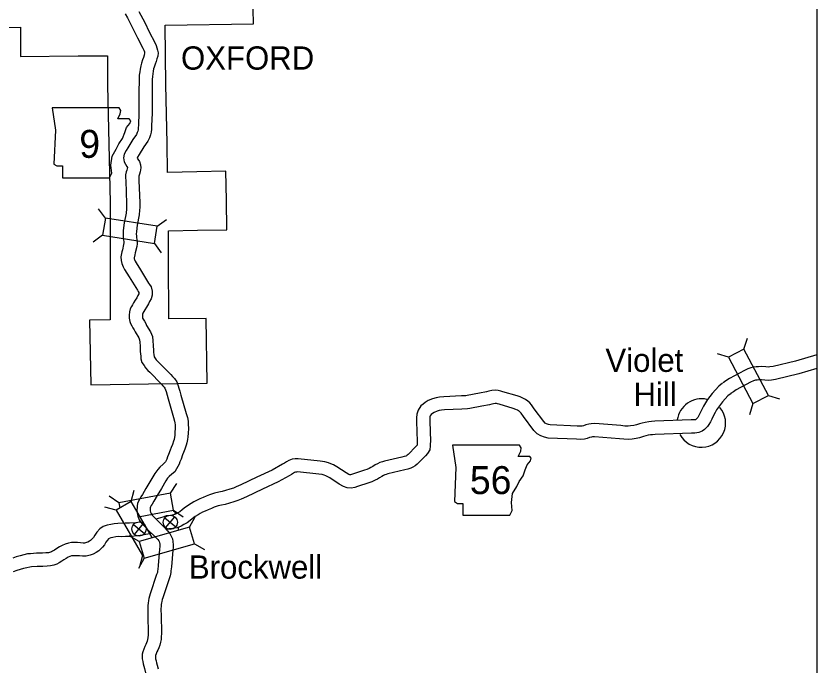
# Model space of a CAD drawing. Extents: x 1377389 to 1380723, y 1168351 to 1170484.
# Drawn here: x 1378097.6 to 1378279.2, y 1169964.7 to 1170112.1 of the extents above; entities that cross this region are included whole.
import ezdxf

# ---------------------------------------------------------------- set-up
doc = ezdxf.new("R2010")
doc.units = 0
doc.layers.add('B_Fill', color=7, linetype='Continuous')
doc.layers.add('B_Text', color=7, linetype='Continuous')

msp = doc.modelspace()

# ---------------------------------------------------------------- linework, layer by layer
at = {"layer": 'B_Fill'}
for p, q in [((1378117.86, 1170066.24), (1378116.31, 1170068.37)), ((1378129.59, 1170064.38), (1378131.73, 1170065.93)), ((1378117.24, 1170062.33), (1378115.1, 1170060.78)), ((1378128.97, 1170060.47), (1378130.52, 1170058.33)), ((1378262.6, 1170036.5), (1378263.38, 1170039.02)), ((1378259.09, 1170034.66), (1378256.57, 1170035.44)), ((1378268.13, 1170025.99), (1378270.65, 1170025.21)), ((1378264.62, 1170024.15), (1378263.84, 1170021.62)), ((1378132.59, 1170003.85), (1378134.08, 1170006.03)), ((1378120.91, 1170001.67), (1378118.74, 1170003.16)), ((1378132.59, 1170003.85), (1378120.91, 1170001.67)), ((1378123.74, 1170001.98), (1378124.42, 1170004.53)), ((1378133.32, 1169999.96), (1378132.59, 1170003.85)), ((1378123.74, 1170001.98), (1378120.31, 1169999.99)), ((1378120.91, 1170001.67), (1378121.13, 1170000.53)), ((1378128.46, 1169993.82), (1378123.74, 1170001.98)), ((1378120.31, 1169999.99), (1378117.76, 1170000.68)), ((1378120.31, 1169999.99), (1378126.26, 1169989.71)), ((1378125.75, 1169998.54), (1378133.32, 1169999.96)), ((1378133.32, 1169999.96), (1378135.5, 1169998.46)), ((1378131.32, 1169998.28), (1378133.81, 1169996.19)), ((1378131.52, 1169995.99), (1378133.61, 1169998.48)), ((1378136.96, 1169996.14), (1378138.24, 1169998.45)), ((1378124.24, 1169996.77), (1378126.73, 1169994.68)), ((1378124.44, 1169994.48), (1378126.53, 1169996.97)), ((1378136.96, 1169996.14), (1378125.53, 1169992.88)), ((1378138.04, 1169992.33), (1378136.96, 1169996.14)), ((1378125.53, 1169992.88), (1378123.23, 1169994.16)), ((1378125.53, 1169992.88), (1378126.62, 1169989.07)), ((1378126.62, 1169989.07), (1378138.04, 1169992.33)), ((1378138.04, 1169992.33), (1378140.35, 1169991.05)), ((1378126.62, 1169989.07), (1378125.34, 1169986.76)), ((1378126.26, 1169989.71), (1378125.58, 1169987.16)), ((1378126.26, 1169989.71), (1378126.37, 1169989.78))]:
    msp.add_line(p, q, dxfattribs=at)
for points in [[(1378145.34, 1170070.27), (1378145.19, 1170076.89), (1378138.59, 1170076.75), (1378131.98, 1170076.61), (1378131.84, 1170083.24), (1378131.57, 1170096.49), (1378131.44, 1170109.98), (1378151.44, 1170110.32), (1378151.3, 1170117.04)], [(1378122.31, 1170112.59), (1378122.84, 1170111.64), (1378124.1, 1170109.24), (1378125.12, 1170107.14), (1378126.36, 1170104.8), (1378126.56, 1170104.3), (1378126.7, 1170103.94), (1378126.75, 1170103.75), (1378126.77, 1170103.63), (1378126.76, 1170103.53), (1378126.66, 1170103.21), (1378126.5, 1170102.68), (1378126.29, 1170102.12), (1378126.04, 1170101.37), (1378125.87, 1170100.74), (1378125.74, 1170100.04), (1378125.64, 1170099.41), (1378125.55, 1170098.62), (1378125.5, 1170097.77), (1378125.49, 1170096.62), (1378125.48, 1170095.77), (1378125.44, 1170090.12), (1378125.35, 1170087.29), (1378125.32, 1170086.69), (1378125.27, 1170086.26), (1378125.2, 1170085.95), (1378125.1, 1170085.65), (1378124.88, 1170085.23), (1378124.06, 1170084.03), (1378122.92, 1170082.18), (1378122.54, 1170081.53), (1378122.1, 1170080.73), (1378121.96, 1170079.9), (1378122.11, 1170079.02), (1378122.41, 1170078.43), (1378122.7, 1170077.97), (1378122.85, 1170077.74), (1378122.84, 1170077.7), (1378122.79, 1170077.38), (1378122.72, 1170077.12), (1378122.6, 1170076.76), (1378122.46, 1170076.02), (1378122.46, 1170075.46), (1378122.47, 1170074.69), (1378122.64, 1170069.58), (1378122.68, 1170068.75), (1378122.63, 1170068.34), (1378122.56, 1170067.36), (1378122.11, 1170065.14), (1378121.89, 1170063.39), (1378121.86, 1170062.58), (1378121.89, 1170062.11), (1378121.9, 1170061.61), (1378121.96, 1170061.22), (1378122.01, 1170060.94), (1378122.04, 1170060.74), (1378122.04, 1170060.64), (1378122, 1170060.28), (1378121.74, 1170059.04), (1378121.61, 1170058.6), (1378121.4, 1170057.47), (1378121.42, 1170056.61), (1378121.59, 1170055.91), (1378121.9, 1170055.17), (1378122.22, 1170054.57), (1378123.26, 1170052.92), (1378125.12, 1170049.87), (1378125.33, 1170049.55), (1378125.44, 1170049.39), (1378125.45, 1170049.34), (1378125.45, 1170049.17), (1378125.42, 1170049.07), (1378125.21, 1170048.71), (1378124.97, 1170048.15), (1378124.65, 1170047.61), (1378124.24, 1170046.99), (1378124.01, 1170046.57), (1378123.77, 1170046.21), (1378123.48, 1170045.63), (1378123.3, 1170044.96), (1378123.24, 1170044.23), (1378123.24, 1170043.54), (1378123.38, 1170042.77), (1378123.54, 1170042.32)], [(1378125.48, 1170113.07), (1378126.78, 1170110.59), (1378127.8, 1170108.5), (1378129.09, 1170106.07), (1378129.35, 1170105.4), (1378129.56, 1170104.88), (1378129.7, 1170104.33), (1378129.79, 1170103.68), (1378129.72, 1170102.95), (1378129.53, 1170102.34), (1378129.34, 1170101.72), (1378129.12, 1170101.11), (1378128.91, 1170100.5), (1378128.8, 1170100.09), (1378128.7, 1170099.52), (1378128.61, 1170098.99), (1378128.54, 1170098.36), (1378128.5, 1170097.67), (1378128.49, 1170096.58), (1378128.48, 1170095.74), (1378128.44, 1170090.06), (1378128.35, 1170087.16), (1378128.31, 1170086.44), (1378128.23, 1170085.74), (1378128.09, 1170085.13), (1378127.87, 1170084.47), (1378127.46, 1170083.69), (1378126.58, 1170082.4), (1378125.5, 1170080.65), (1378125.16, 1170080.06), (1378125.05, 1170079.86), (1378125.21, 1170079.61), (1378125.6, 1170079.04), (1378125.85, 1170078.29), (1378125.89, 1170077.6), (1378125.79, 1170077.15), (1378125.74, 1170076.76), (1378125.59, 1170076.22), (1378125.51, 1170075.99), (1378125.46, 1170075.75), (1378125.46, 1170075.48), (1378125.47, 1170074.75), (1378125.64, 1170069.7), (1378125.69, 1170068.64), (1378125.62, 1170068.06), (1378125.54, 1170066.95), (1378125.07, 1170064.65), (1378124.89, 1170063.16), (1378124.87, 1170062.59), (1378124.88, 1170062.23), (1378124.89, 1170061.87), (1378124.92, 1170061.72), (1378124.97, 1170061.46), (1378125.06, 1170060.87), (1378125.03, 1170060.38), (1378124.96, 1170059.81), (1378124.65, 1170058.32), (1378124.53, 1170057.91), (1378124.41, 1170057.24), (1378124.42, 1170057), (1378124.46, 1170056.83), (1378124.61, 1170056.46), (1378124.81, 1170056.09), (1378125.81, 1170054.5), (1378127.65, 1170051.49), (1378127.85, 1170051.19), (1378128.21, 1170050.61), (1378128.47, 1170049.69), (1378128.43, 1170048.76), (1378128.23, 1170047.92), (1378127.89, 1170047.34), (1378127.65, 1170046.79), (1378127.2, 1170046.03), (1378126.82, 1170045.45), (1378126.59, 1170045.02), (1378126.36, 1170044.69), (1378126.29, 1170044.55), (1378126.27, 1170044.46), (1378126.24, 1170044.1), (1378126.24, 1170043.8), (1378126.28, 1170043.56)], [(1378085.32, 1170109.32), (1378098.59, 1170109.52)], [(1378098.59, 1170109.52), (1378098.62, 1170102.9), (1378111.73, 1170103), (1378118.31, 1170103.06), (1378118.38, 1170096.34), (1378118.91, 1170069.75), (1378118.97, 1170043.17), (1378114.24, 1170043.12)], [(1378114.24, 1170043.12), (1378114.6, 1170028.45), (1378127.6, 1170028.66), (1378140.95, 1170028.82), (1378140.67, 1170043.48), (1378132.25, 1170043.36), (1378132.18, 1170056.67), (1378132.15, 1170063.33), (1378138.78, 1170063.46), (1378145.4, 1170063.59), (1378145.34, 1170070.27)], [(1378126.28, 1170043.56), (1378126.43, 1170043.3), (1378126.71, 1170042.85), (1378127, 1170042.3), (1378127.22, 1170041.9), (1378128.11, 1170040.42), (1378128.52, 1170039.4), (1378128.63, 1170038.4), (1378128.71, 1170037.34), (1378128.75, 1170036.19), (1378128.79, 1170035.86), (1378128.88, 1170035.2), (1378128.9, 1170034.81), (1378128.92, 1170034.76), (1378129.08, 1170034.53), (1378129.37, 1170034.11), (1378129.66, 1170033.77), (1378130, 1170033.45), (1378132.67, 1170030.74), (1378133.09, 1170030.28), (1378133.54, 1170029.82), (1378134.03, 1170029.09), (1378134.38, 1170028.21), (1378134.52, 1170027.65), (1378134.72, 1170026.96), (1378134.99, 1170026.05), (1378136.14, 1170021.92), (1378136.46, 1170020.98), (1378136.62, 1170020.17), (1378136.64, 1170019.5), (1378136.7, 1170018.53), (1378136.64, 1170017.47), (1378136.56, 1170016.66), (1378136.5, 1170016.02), (1378136.32, 1170015.28), (1378136.16, 1170014.72), (1378135.86, 1170013.84), (1378135.54, 1170013.1), (1378135.34, 1170012.57), (1378135.01, 1170011.58), (1378134.77, 1170010.98), (1378134.56, 1170010.42), (1378134.31, 1170009.87), (1378134.02, 1170009.35), (1378133.57, 1170008.72), (1378132.95, 1170008.19), (1378132.35, 1170007.6), (1378131.98, 1170007.23), (1378131.54, 1170006.68), (1378130.56, 1170004.9), (1378129.61, 1170003.31), (1378128.83, 1170002.04), (1378128.46, 1170001.38), (1378128.23, 1170001.06), (1378128.14, 1170000.88), (1378128.08, 1170000.71), (1378128.05, 1170000.55), (1378128.01, 1170000.27), (1378128, 1170000.1), (1378128.03, 1169999.85), (1378128.1, 1169999.52), (1378128.21, 1169999.22), (1378128.47, 1169998.84), (1378129.15, 1169998.15), (1378129.91, 1169997.39)], [(1378123.54, 1170042.32), (1378123.84, 1170041.78), (1378124.11, 1170041.34), (1378124.36, 1170040.89), (1378124.6, 1170040.42), (1378125.41, 1170039.08), (1378125.58, 1170038.66), (1378125.64, 1170038.12), (1378125.71, 1170037.18), (1378125.76, 1170035.95), (1378125.81, 1170035.48), (1378125.89, 1170034.9), (1378125.93, 1170034.32), (1378126.16, 1170033.47), (1378126.62, 1170032.81), (1378126.99, 1170032.28), (1378127.49, 1170031.69), (1378127.92, 1170031.3), (1378130.49, 1170028.68), (1378130.91, 1170028.22), (1378131.2, 1170027.92), (1378131.36, 1170027.69), (1378131.52, 1170027.29), (1378131.62, 1170026.87), (1378131.85, 1170026.11), (1378132.1, 1170025.23), (1378133.27, 1170021.02), (1378133.56, 1170020.21), (1378133.63, 1170019.82), (1378133.65, 1170019.35), (1378133.7, 1170018.54), (1378133.64, 1170017.7), (1378133.58, 1170016.93), (1378133.54, 1170016.53), (1378133.42, 1170016.05), (1378133.3, 1170015.61), (1378133.06, 1170014.91), (1378132.77, 1170014.23), (1378132.52, 1170013.59), (1378132.19, 1170012.6), (1378131.98, 1170012.06), (1378131.8, 1170011.58), (1378131.63, 1170011.22), (1378131.48, 1170010.95), (1378131.35, 1170010.77), (1378130.93, 1170010.41), (1378130.24, 1170009.73), (1378129.73, 1170009.23), (1378129.04, 1170008.34), (1378127.96, 1170006.39), (1378127.04, 1170004.87), (1378126.24, 1170003.56), (1378125.92, 1170002.99), (1378125.64, 1170002.59), (1378125.38, 1170002.06), (1378125.17, 1170001.48), (1378125.09, 1170001.01), (1378125.03, 1170000.61), (1378124.99, 1170000.07), (1378125.06, 1169999.39), (1378125.21, 1169998.64), (1378125.55, 1169997.8), (1378126.14, 1169996.93), (1378127.02, 1169996.04), (1378127.8, 1169995.25)], [(1378279.16, 1170035.23), (1378274.3, 1170033.8), (1378269.23, 1170032.59), (1378268.5, 1170032.49), (1378268.09, 1170032.45), (1378267.54, 1170032.49), (1378266.64, 1170032.54), (1378265.87, 1170032.53), (1378265.34, 1170032.5), (1378264.73, 1170032.42), (1378264.15, 1170032.31), (1378263.5, 1170032.05), (1378262.73, 1170031.65), (1378259.29, 1170029.84), (1378258.52, 1170029.33), (1378257.86, 1170028.87)], [(1378279.16, 1170032.1), (1378275.08, 1170030.9), (1378269.78, 1170029.63), (1378268.86, 1170029.51), (1378268.12, 1170029.43), (1378267.34, 1170029.5), (1378266.58, 1170029.54), (1378265.97, 1170029.53), (1378265.63, 1170029.51), (1378265.2, 1170029.45), (1378264.99, 1170029.41), (1378264.75, 1170029.32), (1378264.12, 1170028.99), (1378260.82, 1170027.26), (1378260.22, 1170026.86), (1378259.59, 1170026.42)], [(1378257.77, 1170028.8), (1378256.93, 1170028.1), (1378256.17, 1170027.32), (1378255.41, 1170026.47), (1378254.87, 1170025.76), (1378254.37, 1170025.08), (1378253.86, 1170024.31), (1378253.43, 1170023.56), (1378252.98, 1170022.65), (1378252.66, 1170022.03), (1378252.36, 1170021.43), (1378252.12, 1170021.01), (1378252, 1170020.83), (1378251.87, 1170020.7), (1378251.77, 1170020.6), (1378251.67, 1170020.53), (1378251.59, 1170020.5), (1378251.28, 1170020.46), (1378250.65, 1170020.46), (1378242.37, 1170020.14), (1378241.68, 1170020.11), (1378241.05, 1170020.05), (1378240.22, 1170019.91), (1378239.53, 1170019.72), (1378238.92, 1170019.54), (1378238.22, 1170019.32), (1378237.66, 1170019.21), (1378236.87, 1170019.1), (1378236.36, 1170019.04), (1378235.59, 1170019.06), (1378234.72, 1170019.16), (1378228.79, 1170019.64), (1378227.94, 1170019.59), (1378227.41, 1170019.5), (1378226.77, 1170019.32), (1378226.23, 1170019.15), (1378225.91, 1170019.06), (1378225.51, 1170019.02), (1378224.8, 1170019.06), (1378218.69, 1170019.31), (1378218.27, 1170019.41), (1378217.87, 1170019.56), (1378217.56, 1170019.74), (1378217.21, 1170020.08), (1378215.09, 1170022.96), (1378214.43, 1170023.88), (1378214.04, 1170024.31), (1378213.63, 1170024.73), (1378213.11, 1170025.11), (1378212.51, 1170025.41), (1378211.88, 1170025.66), (1378211.17, 1170025.89), (1378207.97, 1170026.86), (1378207.49, 1170027.01), (1378206.88, 1170027.13), (1378206.21, 1170027.18), (1378205.46, 1170027.11), (1378204.76, 1170026.98), (1378204.24, 1170026.83), (1378202.66, 1170026.55)], [(1378202.64, 1170026.54), (1378199.88, 1170026), (1378199.58, 1170025.93), (1378198.58, 1170025.92), (1378194.55, 1170025.73), (1378193.62, 1170025.65), (1378192.82, 1170025.5), (1378192.01, 1170025.25), (1378191.02, 1170024.83), (1378190.36, 1170024.42), (1378189.86, 1170024.06), (1378189.39, 1170023.64), (1378188.75, 1170022.68), (1378188.47, 1170021.76), (1378188.38, 1170020.93), (1378188.41, 1170020.08), (1378188.52, 1170015.59), (1378188.5, 1170015.1), (1378188.5, 1170014.75), (1378188.49, 1170014.65), (1378188.26, 1170014.41), (1378186.49, 1170012.64), (1378186.26, 1170012.44), (1378186.1, 1170012.34), (1378185.97, 1170012.27), (1378185.62, 1170012.16), (1378185.07, 1170012.03), (1378181.16, 1170011.11), (1378180.64, 1170010.97), (1378180.09, 1170010.78), (1378179.53, 1170010.52), (1378179.04, 1170010.25), (1378178.49, 1170009.93), (1378178.02, 1170009.66), (1378177.67, 1170009.46), (1378177.13, 1170009.23), (1378176.6, 1170009.03), (1378174.12, 1170008.22), (1378173.63, 1170008.07), (1378173.39, 1170008.02), (1378173.27, 1170008.03), (1378173.03, 1170008.11), (1378172.45, 1170008.43), (1378170.34, 1170009.84), (1378169.6, 1170010.26), (1378168.98, 1170010.53), (1378168.41, 1170010.76), (1378167.61, 1170010.99), (1378166.58, 1170011.14), (1378161.56, 1170011.65), (1378160.91, 1170011.64), (1378160.22, 1170011.54), (1378159.48, 1170011.27), (1378158.9, 1170010.95), (1378158.45, 1170010.63), (1378158.04, 1170010.4), (1378155.66, 1170009.1), (1378152.18, 1170007.49), (1378148.55, 1170005.72), (1378147.51, 1170005.25), (1378146.87, 1170005.01), (1378146.05, 1170004.75), (1378145.1, 1170004.45), (1378144.34, 1170004.23), (1378143.55, 1170004.08), (1378142.56, 1170003.82), (1378141.46, 1170003.46), (1378140.72, 1170003.16), (1378140, 1170002.84), (1378139.28, 1170002.53), (1378138.55, 1170002.22), (1378137.89, 1170001.87), (1378137.28, 1170001.5), (1378136.51, 1170000.99), (1378135.75, 1170000.42), (1378135.29, 1170000.06), (1378134.71, 1169999.65), (1378134.15, 1169999.31), (1378133.76, 1169999.08), (1378133.27, 1169998.9), (1378132.71, 1169998.77), (1378131.65, 1169998.68), (1378130.9, 1169998.43), (1378129.84, 1169998.11), (1378129.32, 1169997.97)], [(1378259.68, 1170026.48), (1378258.97, 1170025.9), (1378258.36, 1170025.27), (1378257.72, 1170024.56), (1378257.28, 1170023.97), (1378256.83, 1170023.36), (1378256.41, 1170022.73), (1378256.08, 1170022.15), (1378255.66, 1170021.3), (1378255.33, 1170020.65), (1378255, 1170020.02), (1378254.67, 1170019.43), (1378254.34, 1170018.95), (1378254, 1170018.58), (1378253.66, 1170018.26), (1378253.12, 1170017.88), (1378252.35, 1170017.57), (1378251.45, 1170017.46), (1378250.7, 1170017.46), (1378242.51, 1170017.15), (1378241.9, 1170017.11), (1378241.43, 1170017.07), (1378240.86, 1170016.98), (1378240.37, 1170016.84), (1378239.8, 1170016.67), (1378238.96, 1170016.41), (1378238.15, 1170016.25), (1378237.27, 1170016.13), (1378236.52, 1170016.03), (1378235.38, 1170016.06), (1378234.42, 1170016.17), (1378228.76, 1170016.63), (1378228.29, 1170016.6), (1378228.06, 1170016.56), (1378227.62, 1170016.44), (1378227.1, 1170016.28), (1378226.46, 1170016.09), (1378225.55, 1170016.02), (1378224.66, 1170016.06), (1378218.25, 1170016.32), (1378217.38, 1170016.55), (1378216.59, 1170016.84), (1378215.75, 1170017.32), (1378214.95, 1170018.09), (1378212.67, 1170021.2), (1378212.11, 1170021.98), (1378211.86, 1170022.25), (1378211.66, 1170022.45), (1378211.53, 1170022.55), (1378211.29, 1170022.67), (1378210.87, 1170022.83), (1378210.26, 1170023.03), (1378207.09, 1170024), (1378206.76, 1170024.1), (1378206.49, 1170024.15), (1378206.24, 1170024.17), (1378205.86, 1170024.13), (1378205.44, 1170024.06), (1378204.92, 1170023.91), (1378203.2, 1170023.6)], [(1378203.22, 1170023.6), (1378200.48, 1170023.06), (1378199.91, 1170022.94), (1378198.67, 1170022.92), (1378194.75, 1170022.73), (1378194.02, 1170022.67), (1378193.54, 1170022.59), (1378193.04, 1170022.43), (1378192.41, 1170022.16), (1378192.04, 1170021.93), (1378191.74, 1170021.72), (1378191.68, 1170021.66), (1378191.49, 1170021.38), (1378191.42, 1170021.15), (1378191.38, 1170020.81), (1378191.41, 1170020.17), (1378191.52, 1170015.57), (1378191.5, 1170015.04), (1378191.5, 1170014.57), (1378191.39, 1170013.67), (1378190.9, 1170012.84), (1378190.4, 1170012.31), (1378188.54, 1170010.45), (1378188.08, 1170010.05), (1378187.58, 1170009.72), (1378187.09, 1170009.48), (1378186.43, 1170009.27), (1378185.76, 1170009.11), (1378181.9, 1170008.2), (1378181.53, 1170008.1), (1378181.21, 1170007.99), (1378180.89, 1170007.84), (1378180.52, 1170007.64), (1378179.99, 1170007.33), (1378179.51, 1170007.05), (1378179.01, 1170006.77), (1378178.26, 1170006.45), (1378177.6, 1170006.2), (1378175.02, 1170005.36), (1378174.39, 1170005.16), (1378173.57, 1170004.99), (1378172.65, 1170005.07), (1378171.82, 1170005.35), (1378170.88, 1170005.87), (1378168.76, 1170007.29), (1378168.25, 1170007.58), (1378167.83, 1170007.76), (1378167.44, 1170007.91), (1378166.97, 1170008.05), (1378166.21, 1170008.16), (1378161.44, 1170008.65), (1378161.15, 1170008.64), (1378160.96, 1170008.62), (1378160.73, 1170008.53), (1378160.5, 1170008.41), (1378160.08, 1170008.1), (1378159.5, 1170007.77), (1378157.01, 1170006.42), (1378153.47, 1170004.78), (1378149.83, 1170003.01), (1378148.65, 1170002.48), (1378147.87, 1170002.18), (1378146.96, 1170001.89), (1378145.96, 1170001.58), (1378145.04, 1170001.31), (1378144.22, 1170001.15), (1378143.4, 1170000.94), (1378142.5, 1170000.65), (1378141.91, 1170000.4), (1378141.19, 1170000.08), (1378140.46, 1169999.77), (1378139.85, 1169999.51), (1378139.36, 1169999.25), (1378138.89, 1169998.97), (1378138.24, 1169998.53), (1378137.57, 1169998.04), (1378137.08, 1169997.66), (1378136.37, 1169997.15), (1378135.68, 1169996.72), (1378135.04, 1169996.36), (1378134.14, 1169996.02), (1378133.16, 1169995.8), (1378132.27, 1169995.72), (1378131.75, 1169995.55)], [(1378125.88, 1169997.32), (1378124.88, 1169997.14), (1378123.36, 1169997.01), (1378122.33, 1169997.03), (1378120.65, 1169996.99), (1378119.84, 1169996.89), (1378119.07, 1169996.77), (1378118.25, 1169996.61), (1378117.34, 1169996.25), (1378116.6, 1169995.77), (1378115.96, 1169995.03), (1378115.46, 1169994.33), (1378115.16, 1169993.81), (1378114.97, 1169993.58), (1378114.49, 1169993.11), (1378114.25, 1169992.94), (1378113.87, 1169992.74), (1378113.56, 1169992.63), (1378113.15, 1169992.53), (1378112.82, 1169992.53), (1378112.24, 1169992.59), (1378111.58, 1169992.63), (1378110.92, 1169992.66), (1378110.22, 1169992.64), (1378109.54, 1169992.54), (1378108.74, 1169992.3), (1378108.05, 1169991.98), (1378107.47, 1169991.64), (1378106.85, 1169991.28), (1378106.34, 1169990.93), (1378105.91, 1169990.67), (1378105.64, 1169990.52), (1378105.43, 1169990.46), (1378104.94, 1169990.35), (1378104.37, 1169990.29), (1378103.59, 1169990.22), (1378102.27, 1169990.24), (1378100.87, 1169990.11), (1378100.23, 1169990.06), (1378099.36, 1169989.85), (1378098.53, 1169989.65), (1378097.66, 1169989.39), (1378096.9, 1169989.13)], [(1378129.91, 1169997.39), (1378131.09, 1169996.23), (1378131.98, 1169995.31), (1378132.47, 1169994.71), (1378132.79, 1169994.11), (1378133.04, 1169993.47), (1378133.17, 1169992.87), (1378133.24, 1169992.14), (1378133.19, 1169991.54), (1378133.16, 1169990.92), (1378132.84, 1169987.13), (1378132.72, 1169986.24), (1378132.68, 1169985.82), (1378132.55, 1169985.13), (1378132.32, 1169984.45), (1378130.87, 1169980.1), (1378130.76, 1169979.74), (1378130.66, 1169979.3), (1378130.58, 1169978.95), (1378130.53, 1169978.62), (1378130.51, 1169978.16), (1378130.46, 1169977.69), (1378130.46, 1169977.14), (1378130.47, 1169976.43), (1378130.55, 1169971.84)], [(1378128.36, 1169994.71), (1378125.27, 1169994.17), (1378123.47, 1169994.01), (1378122.4, 1169994.03), (1378121.49, 1169993.98), (1378120.82, 1169993.99), (1378120.25, 1169993.92), (1378119.57, 1169993.82), (1378119.1, 1169993.72), (1378118.72, 1169993.57), (1378118.59, 1169993.49), (1378118.32, 1169993.17), (1378117.98, 1169992.7), (1378117.64, 1169992.11), (1378117.2, 1169991.57), (1378116.41, 1169990.78), (1378115.81, 1169990.37), (1378115.08, 1169989.98), (1378114.41, 1169989.75), (1378113.51, 1169989.53), (1378112.67, 1169989.53), (1378111.98, 1169989.6), (1378111.4, 1169989.64), (1378110.92, 1169989.66), (1378110.5, 1169989.64), (1378110.18, 1169989.6), (1378109.8, 1169989.49), (1378109.44, 1169989.32), (1378108.98, 1169989.05), (1378108.45, 1169988.74), (1378107.96, 1169988.41), (1378107.42, 1169988.08), (1378106.83, 1169987.75), (1378106.2, 1169987.55), (1378105.43, 1169987.39), (1378104.67, 1169987.3), (1378103.69, 1169987.22), (1378102.39, 1169987.24), (1378101.13, 1169987.12), (1378100.72, 1169987.09), (1378100.07, 1169986.93), (1378099.31, 1169986.75), (1378098.57, 1169986.53), (1378097.8, 1169986.27), (1378096.95, 1169986.02)], [(1378127.8, 1169995.25), (1378128.97, 1169994.11), (1378129.74, 1169993.31), (1378129.96, 1169993.05), (1378130.06, 1169992.86), (1378130.16, 1169992.59), (1378130.2, 1169992.41), (1378130.23, 1169992.14), (1378130.19, 1169991.75), (1378130.16, 1169991.12), (1378129.86, 1169987.46), (1378129.74, 1169986.57), (1378129.71, 1169986.22), (1378129.64, 1169985.89), (1378129.48, 1169985.4), (1378128.01, 1169981), (1378127.86, 1169980.49), (1378127.74, 1169979.96), (1378127.63, 1169979.51), (1378127.55, 1169978.93), (1378127.52, 1169978.38), (1378127.46, 1169977.84), (1378127.46, 1169977.14), (1378127.47, 1169976.39), (1378127.55, 1169971.7)], [(1378127.55, 1169971.7), (1378127.5, 1169971.02), (1378127.43, 1169970.65), (1378127.34, 1169970.28), (1378127.19, 1169969.9), (1378127.04, 1169969.52), (1378126.81, 1169969.09), (1378126.58, 1169968.48), (1378126.34, 1169967.89), (1378126.23, 1169967.3), (1378126.2, 1169966.69), (1378126.22, 1169966.24), (1378126.32, 1169965.69), (1378126.44, 1169965.17), (1378126.57, 1169964.63), (1378126.71, 1169964.09), (1378126.96, 1169963.12)], [(1378130.55, 1169971.84), (1378130.53, 1169971.39), (1378130.48, 1169970.63), (1378130.36, 1169970.03), (1378130.21, 1169969.39), (1378129.98, 1169968.77), (1378129.75, 1169968.23), (1378129.55, 1169967.86), (1378129.38, 1169967.4), (1378129.24, 1169967.05), (1378129.22, 1169966.95), (1378129.2, 1169966.69), (1378129.21, 1169966.58), (1378129.26, 1169966.28), (1378129.36, 1169965.85), (1378129.47, 1169965.37), (1378129.61, 1169964.86), (1378129.84, 1169963.99)]]:
    msp.add_lwpolyline(points, dxfattribs=at)
for points in [[(1378105.77, 1170091.26), (1378106.53, 1170086.18), (1378106.19, 1170078.48), (1378106.87, 1170078.06), (1378108.13, 1170078.06), (1378108.13, 1170075.35), (1378118.79, 1170075.35), (1378119.3, 1170076.45), (1378119.13, 1170078.23), (1378119.38, 1170080.26), (1378120.31, 1170081.87), (1378120.91, 1170083.05), (1378121.75, 1170084.32), (1378122.26, 1170085.67), (1378122.68, 1170086.77), (1378123.44, 1170087.7), (1378123.61, 1170088.3), (1378123.28, 1170088.72), (1378120.65, 1170088.72), (1378121.25, 1170089.9), (1378121.33, 1170090.66), (1378120.98, 1170091.25)], [(1378117.24, 1170062.33), (1378128.97, 1170060.47), (1378129.59, 1170064.38), (1378117.86, 1170066.24)], [(1378268.13, 1170025.99), (1378262.6, 1170036.5), (1378259.09, 1170034.66), (1378264.62, 1170024.15)], [(1378196.55, 1170014.73), (1378197.31, 1170009.66), (1378196.97, 1170001.96), (1378197.65, 1170001.54), (1378198.91, 1170001.54), (1378198.91, 1169998.83), (1378209.57, 1169998.83), (1378210.08, 1169999.93), (1378209.91, 1170001.7), (1378210.16, 1170003.74), (1378211.09, 1170005.34), (1378211.69, 1170006.53), (1378212.53, 1170007.8), (1378213.04, 1170009.15), (1378213.46, 1170010.25), (1378214.22, 1170011.18), (1378214.39, 1170011.77), (1378214.06, 1170012.19), (1378211.43, 1170012.19), (1378212.03, 1170013.38), (1378212.11, 1170014.14), (1378211.76, 1170014.72)]]:
    msp.add_lwpolyline(points, close=True, dxfattribs=at)
for centre in [(1378125.49, 1169995.72), (1378132.57, 1169997.24)]:
    msp.add_circle(centre, 1.62, dxfattribs=at)
for centre, start, end in [((1378252.95, 1170019.75), 76.9385, 172.4927), ((1378252.95, 1170019.75), 207.943, 40.3467), ((1378129.01, 1169996.49), 29.2258, 38.1698), ((1378129.01, 1169996.49), 349.5166, 355.7882)]:
    msp.add_arc(centre, 5.5, start, end, dxfattribs=at)
at = {"layer": 'B_Text'}
msp.add_lwpolyline([(1377549.76, 1170388.77), (1378279.16, 1170388.77), (1378279.16, 1169604.28), (1377549.76, 1169604.28)], close=True, dxfattribs=at)

# ---------------------------------------------------------------- texts
at = {"layer": 'B_Fill'}
for s, height, p in [('OXFORD', 5.28, (1378135, 1170099.9)), ('9', 6.34, (1378111.95, 1170079.9)), ('Violet', 5.28, (1378231.2, 1170031.35)), ('Hill', 5.28, (1378237.56, 1170023.63)), ('56', 6.336, (1378200.48, 1170003.64)), ('Brockwell', 5.28, (1378136.79, 1169984.46))]:
    msp.add_text(s, height=height, dxfattribs=at).set_placement(p)

doc.saveas('drawing.dxf')
